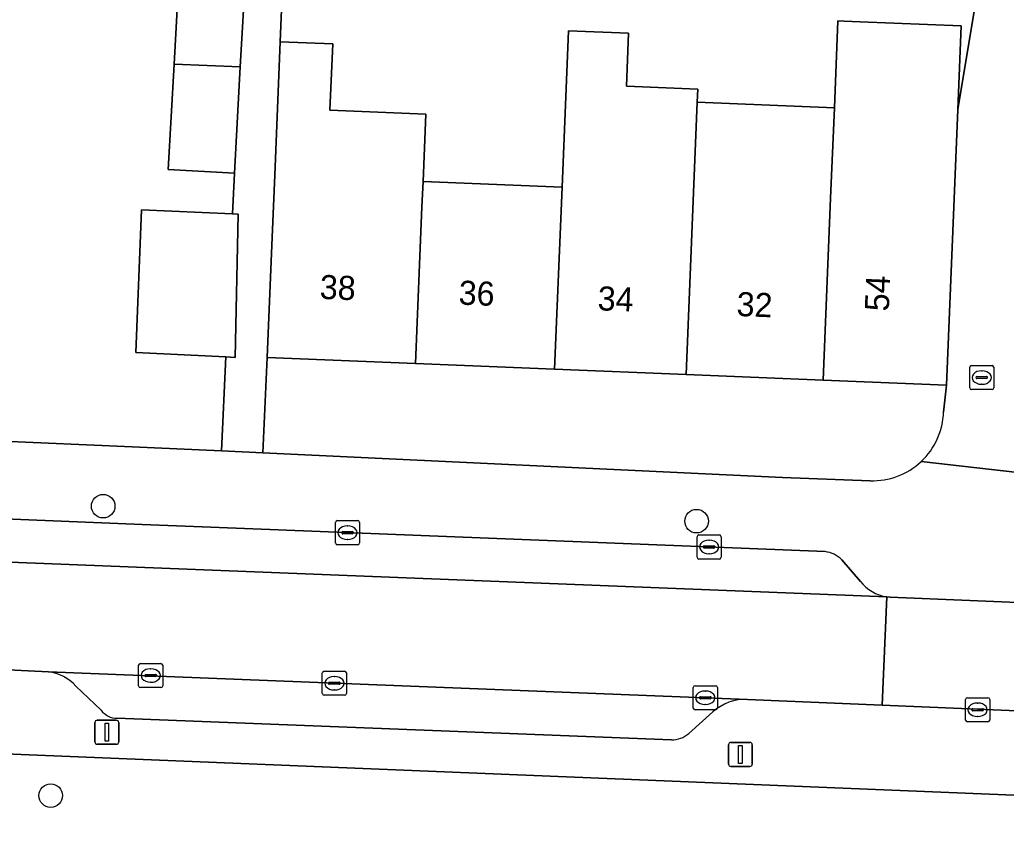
# Model space of a CAD drawing. Extents: x 159817 to 160765, y 380688 to 381638.
# Drawn here: x 160007.42 to 160048.41, y 380865.33 to 380898.7 of the extents above; entities that cross this region are included whole.
import ezdxf

# ---------------------------------------------------------------- set-up
doc = ezdxf.new("R2010")
doc.units = 0
for name, color, linetype in [('IMGEO_Berm_groen', 7, 'Continuous'), ('IMGEO_Boom', 7, 'Continuous'), ('IMGEO_Brandkraan', 7, 'Continuous'), ('IMGEO_Erf', 7, 'Continuous'), ('IMGEO_Kolk', 7, 'Continuous'), ('IMGEO_Lichtmast', 7, 'Continuous'), ('IMGEO_Muur', 7, 'Continuous'), ('IMGEO_Pand', 7, 'Continuous'), ('IMGEO_Pand_nummerreeks', 7, 'Continuous'), ('IMGEO_Parkeervlak_open', 7, 'Continuous'), ('IMGEO_Rijbaan_lokaal_open', 7, 'Continuous'), ('IMGEO_Rioolput', 7, 'Continuous'), ('IMGEO_Voetpad_open', 7, 'Continuous')]:
    doc.layers.add(name, color=color, linetype=linetype)

msp = doc.modelspace()

# ---------------------------------------------------------------- linework, layer by layer
at = {"layer": 'IMGEO_Berm_groen'}
msp.add_lwpolyline([(160170.952, 380848.196), (160169.444, 380861.549), (160005.773, 380868.257), (159996.586, 380868.629), (159996.603, 380869.516), (159993.946, 380869.644), (159993.895, 380868.739), (159985.923, 380869.026)], dxfattribs=at)
at = {"layer": 'IMGEO_Boom'}
for centre in [(160010.889, 380878.497), (160035.543, 380877.875), (160008.708, 380866.477)]:
    msp.add_circle(centre, 0.489, dxfattribs=at)
at = {"layer": 'IMGEO_Brandkraan'}
for p, q in [((160046.891, 380883.415), (160046.891, 380884.267)), ((160046.966, 380884.341), (160047.818, 380884.341)), ((160047.379, 380884.121), (160047.404, 380884.121)), ((160047.892, 380884.267), (160047.892, 380883.415)), ((160047.15, 380883.835), (160047.15, 380883.847)), ((160047.588, 380883.798), (160047.19, 380883.798)), ((160047.193, 380883.884), (160047.591, 380883.884)), ((160047.634, 380883.847), (160047.634, 380883.835)), ((160047.818, 380883.341), (160046.966, 380883.341)), ((160047.402, 380883.561), (160047.377, 380883.561))]:
    msp.add_line(p, q, dxfattribs=at)
for points in [[(160046.891, 380883.415), (160046.891, 380884.267)], [(160046.966, 380884.341), (160047.818, 380884.341)], [(160047.892, 380884.267), (160047.892, 380883.415)], [(160047.818, 380883.341), (160046.966, 380883.341)]]:
    msp.add_lwpolyline(points, dxfattribs=at)
for centre, radius, start, end in [((160046.968, 380884.265), 0.0765, 91.552, 178.448), ((160046.968, 380884.265), 0.0765, 91.552, 178.448), ((160047.816, 380884.265), 0.0765, 1.552, 88.448), ((160047.816, 380884.265), 0.0765, 1.552, 88.448), ((160047.19, 380883.844), 0.0403, 85.8775, 175.7526), ((160047.187, 380883.834), 0.0366, 178.938, 274.7102), ((160047.591, 380883.841), 0.043, 264.8664, 352.4533), ((160047.595, 380883.846), 0.0386, 1.7309, 96.639), ((160046.968, 380883.417), 0.0765, 181.552, 268.448), ((160046.968, 380883.417), 0.0765, 181.552, 268.448), ((160047.816, 380883.417), 0.0765, 271.552, 358.448), ((160047.816, 380883.417), 0.0765, 271.552, 358.448)]:
    msp.add_arc(centre, radius, start, end, dxfattribs=at)
for centre, major_axis, ratio, start_param, end_param in [((160047.378, 380883.841), (-0.387, 0.002), 0.722429, 4.712389, 7.853982), ((160047.403, 380883.841), (-0.39, 0.002), 0.717154, 1.570796, 4.712389)]:
    msp.add_ellipse(centre, major_axis=major_axis, ratio=ratio, start_param=start_param, end_param=end_param, dxfattribs=at)
at = {"layer": 'IMGEO_Erf'}
for points in [[(159989.985, 380938.498), (159987.614, 380882.024), (159996.902, 380881.622), (160012.088, 380880.965), (160015.8, 380880.79), (160015.984, 380884.697), (160012.245, 380884.873), (160012.483, 380890.803), (160016.263, 380890.632), (160016.34, 380892.325), (160013.59, 380892.478), (160013.833, 380896.854), (160014.06, 380900.928), (160016.809, 380900.776), (160016.883, 380904.187), (160014.133, 380904.34), (160014.376, 380908.716), (160014.603, 380912.79)], [(160018.787, 380910.907), (160018.244, 380897.786), (160020.426, 380897.696), (160020.312, 380894.948), (160024.293, 380894.783), (160024.178, 380891.985), (160029.955, 380891.748), (160030.22, 380898.242), (160032.718, 380898.14), (160032.628, 380895.941), (160035.594, 380895.82), (160035.572, 380895.281), (160041.268, 380895.047), (160041.416, 380898.652), (160041.675, 380898.642), (160042.335, 380898.615), (160046.538, 380898.442), (160046.395, 380894.967), (160047.716, 380902.893)], [(160045.925, 380883.518), (160040.804, 380883.728), (160035.109, 380883.962), (160029.646, 380884.187), (160023.868, 380884.424), (160017.704, 380884.677), (160017.517, 380880.709), (160039.11, 380879.69), (160042.759, 380879.556)], [(160045.805, 380882.405), (160045.925, 380883.518)]]:
    msp.add_lwpolyline(points, dxfattribs=at)
for centre, radius, start, end in [((160042.866, 380882.495), 2.94, 313.0697, 358.2481), ((160042.866, 380882.492), 2.938, 267.9062, 313.1049)]:
    msp.add_arc(centre, radius, start, end, dxfattribs=at)
at = {"layer": 'IMGEO_Kolk'}
for p, q in [((160020.616, 380877.897), (160021.468, 380877.897)), ((160020.541, 380876.971), (160020.541, 380877.823)), ((160021.029, 380877.677), (160021.054, 380877.677)), ((160021.542, 380877.823), (160021.542, 380876.971)), ((160020.8, 380877.391), (160020.8, 380877.403)), ((160021.238, 380877.354), (160020.84, 380877.354)), ((160020.843, 380877.44), (160021.241, 380877.44)), ((160021.052, 380877.117), (160021.027, 380877.117)), ((160021.284, 380877.403), (160021.284, 380877.391)), ((160035.563, 380876.377), (160035.563, 380877.229)), ((160035.638, 380877.303), (160036.49, 380877.303)), ((160036.051, 380877.083), (160036.076, 380877.083)), ((160036.564, 380877.229), (160036.564, 380876.377)), ((160021.468, 380876.897), (160020.616, 380876.897)), ((160035.822, 380876.797), (160035.822, 380876.809)), ((160036.26, 380876.76), (160035.862, 380876.76)), ((160035.865, 380876.846), (160036.263, 380876.846)), ((160036.306, 380876.809), (160036.306, 380876.797)), ((160036.49, 380876.303), (160035.638, 380876.303)), ((160036.074, 380876.523), (160036.049, 380876.523)), ((160019.994, 380870.718), (160019.994, 380871.57)), ((160020.069, 380871.644), (160020.921, 380871.644)), ((160020.482, 380871.424), (160020.507, 380871.424)), ((160020.995, 380871.57), (160020.995, 380870.718)), ((160020.253, 380871.138), (160020.253, 380871.15)), ((160020.691, 380871.101), (160020.293, 380871.101)), ((160020.296, 380871.187), (160020.694, 380871.187)), ((160020.737, 380871.15), (160020.737, 380871.138)), ((160035.406, 380870.115), (160035.406, 380870.967)), ((160035.481, 380871.041), (160036.333, 380871.041)), ((160036.407, 380870.967), (160036.407, 380870.115)), ((160020.921, 380870.644), (160020.069, 380870.644)), ((160020.505, 380870.864), (160020.48, 380870.864)), ((160035.665, 380870.535), (160035.665, 380870.547)), ((160035.708, 380870.584), (160036.106, 380870.584)), ((160035.894, 380870.821), (160035.919, 380870.821)), ((160036.149, 380870.547), (160036.149, 380870.535)), ((160036.103, 380870.498), (160035.705, 380870.498)), ((160035.917, 380870.261), (160035.892, 380870.261)), ((160036.333, 380870.041), (160035.481, 380870.041))]:
    msp.add_line(p, q, dxfattribs=at)
for points in [[(160020.616, 380877.897), (160021.468, 380877.897)], [(160020.541, 380876.971), (160020.541, 380877.823)], [(160021.542, 380877.823), (160021.542, 380876.971)], [(160035.563, 380876.377), (160035.563, 380877.229)], [(160035.638, 380877.303), (160036.49, 380877.303)], [(160036.564, 380877.229), (160036.564, 380876.377)], [(160021.468, 380876.897), (160020.616, 380876.897)], [(160036.49, 380876.303), (160035.638, 380876.303)], [(160019.994, 380870.718), (160019.994, 380871.57)], [(160020.069, 380871.644), (160020.921, 380871.644)], [(160020.995, 380871.57), (160020.995, 380870.718)], [(160035.406, 380870.115), (160035.406, 380870.967)], [(160035.481, 380871.041), (160036.333, 380871.041)], [(160036.407, 380870.967), (160036.407, 380870.115)], [(160020.921, 380870.644), (160020.069, 380870.644)], [(160036.333, 380870.041), (160035.481, 380870.041)]]:
    msp.add_lwpolyline(points, dxfattribs=at)
for centre, radius, start, end in [((160020.618, 380877.821), 0.0765, 91.552, 178.448), ((160020.618, 380877.821), 0.0765, 91.552, 178.448), ((160021.466, 380877.821), 0.0765, 1.552, 88.448), ((160021.466, 380877.821), 0.0765, 1.552, 88.448), ((160020.84, 380877.4), 0.0403, 85.8775, 175.7526), ((160020.837, 380877.39), 0.0366, 178.938, 274.7102), ((160021.241, 380877.397), 0.043, 264.8664, 352.4533), ((160021.245, 380877.402), 0.0386, 1.7309, 96.639), ((160035.64, 380877.227), 0.0765, 91.552, 178.448), ((160035.64, 380877.227), 0.0765, 91.552, 178.448), ((160036.488, 380877.227), 0.0765, 1.552, 88.448), ((160036.488, 380877.227), 0.0765, 1.552, 88.448), ((160020.618, 380876.973), 0.0765, 181.552, 268.448), ((160020.618, 380876.973), 0.0765, 181.552, 268.448), ((160021.466, 380876.973), 0.0765, 271.552, 358.448), ((160021.466, 380876.973), 0.0765, 271.552, 358.448), ((160035.862, 380876.806), 0.0403, 85.8775, 175.7526), ((160035.859, 380876.796), 0.0366, 178.938, 274.7102), ((160036.263, 380876.803), 0.043, 264.8664, 352.4533), ((160036.267, 380876.808), 0.0386, 1.7309, 96.639), ((160035.64, 380876.379), 0.0765, 181.552, 268.448), ((160035.64, 380876.379), 0.0765, 181.552, 268.448), ((160036.488, 380876.379), 0.0765, 271.552, 358.448), ((160036.488, 380876.379), 0.0765, 271.552, 358.448), ((160020.071, 380871.568), 0.0765, 91.552, 178.448), ((160020.071, 380871.568), 0.0765, 91.552, 178.448), ((160020.919, 380871.568), 0.0765, 1.552, 88.448), ((160020.919, 380871.568), 0.0765, 1.552, 88.448), ((160020.293, 380871.147), 0.0403, 85.8775, 175.7526), ((160020.29, 380871.137), 0.0366, 178.938, 274.7102), ((160020.694, 380871.144), 0.043, 264.8664, 352.4533), ((160020.698, 380871.149), 0.0386, 1.7309, 96.639), ((160035.483, 380870.965), 0.0765, 91.552, 178.448), ((160035.483, 380870.965), 0.0765, 91.552, 178.448), ((160036.331, 380870.965), 0.0765, 1.552, 88.448), ((160036.331, 380870.965), 0.0765, 1.552, 88.448), ((160020.071, 380870.72), 0.0765, 181.552, 268.448), ((160020.071, 380870.72), 0.0765, 181.552, 268.448), ((160020.919, 380870.72), 0.0765, 271.552, 358.448), ((160020.919, 380870.72), 0.0765, 271.552, 358.448), ((160035.705, 380870.544), 0.0403, 85.8775, 175.7526), ((160035.702, 380870.534), 0.0366, 178.938, 274.7102), ((160036.106, 380870.541), 0.043, 264.8664, 352.4533), ((160036.11, 380870.546), 0.0386, 1.7309, 96.639), ((160035.483, 380870.117), 0.0765, 181.552, 268.448), ((160035.483, 380870.117), 0.0765, 181.552, 268.448), ((160036.331, 380870.117), 0.0765, 271.552, 358.448), ((160036.331, 380870.117), 0.0765, 271.552, 358.448)]:
    msp.add_arc(centre, radius, start, end, dxfattribs=at)
for centre, major_axis, ratio, start_param, end_param in [((160021.028, 380877.397), (-0.387, 0.002), 0.722429, 4.712389, 7.853982), ((160021.053, 380877.397), (-0.39, 0.002), 0.717154, 1.570796, 4.712389), ((160036.05, 380876.803), (-0.387, 0.002), 0.722429, 4.712389, 7.853982), ((160036.075, 380876.803), (-0.39, 0.002), 0.717154, 1.570796, 4.712389), ((160020.481, 380871.144), (-0.387, 0.002), 0.722429, 4.712389, 7.853982), ((160020.506, 380871.144), (-0.39, 0.002), 0.717154, 1.570796, 4.712389), ((160035.893, 380870.541), (-0.387, 0.002), 0.722429, 4.712389, 7.853982), ((160035.918, 380870.541), (-0.39, 0.002), 0.717154, 1.570796, 4.712389)]:
    msp.add_ellipse(centre, major_axis=major_axis, ratio=ratio, start_param=start_param, end_param=end_param, dxfattribs=at)
at = {"layer": 'IMGEO_Lichtmast'}
for p, q in [((160010.545, 380868.707), (160010.545, 380869.507)), ((160010.545, 380869.507), (160010.545, 380868.707)), ((160010.645, 380869.607), (160011.435, 380869.607)), ((160011.435, 380869.607), (160010.645, 380869.607)), ((160011.535, 380869.507), (160011.535, 380868.707)), ((160011.535, 380868.707), (160011.535, 380869.507)), ((160011.435, 380868.607), (160010.645, 380868.607)), ((160010.645, 380868.607), (160011.435, 380868.607)), ((160036.87, 380867.787), (160036.87, 380868.587)), ((160036.87, 380868.587), (160036.87, 380867.787)), ((160036.97, 380868.687), (160037.76, 380868.687)), ((160037.76, 380868.687), (160036.97, 380868.687)), ((160037.86, 380868.587), (160037.86, 380867.787)), ((160037.86, 380867.787), (160037.86, 380868.587)), ((160037.76, 380867.687), (160036.97, 380867.687)), ((160036.97, 380867.687), (160037.76, 380867.687))]:
    msp.add_line(p, q, dxfattribs=at)
for points in [[(160010.965, 380869.482), (160011.115, 380869.482), (160011.115, 380868.732), (160010.965, 380868.732), (160010.965, 380869.482)], [(160037.29, 380868.562), (160037.44, 380868.562), (160037.44, 380867.812), (160037.29, 380867.812), (160037.29, 380868.562)]]:
    msp.add_lwpolyline(points, dxfattribs=at)
for centre, start, end in [((160010.645, 380869.507), 90, 180), ((160010.645, 380869.507), 90, 180), ((160011.435, 380869.507), 0, 90), ((160011.435, 380869.507), 360, 90), ((160010.645, 380868.707), 180, 270), ((160010.645, 380868.707), 180, 270), ((160011.435, 380868.707), 270, 0), ((160011.435, 380868.707), 270, 0), ((160036.97, 380868.587), 90, 180), ((160036.97, 380868.587), 90, 180), ((160037.76, 380868.587), 0, 90), ((160037.76, 380868.587), 360, 90), ((160036.97, 380867.787), 180, 270), ((160036.97, 380867.787), 180, 270), ((160037.76, 380867.787), 270, 0), ((160037.76, 380867.787), 270, 0)]:
    msp.add_arc(centre, 0.1, start, end, dxfattribs=at)
at = {"layer": 'IMGEO_Muur'}
for points in [[(160047.716, 380902.893), (160046.395, 380894.967)], [(160012.088, 380880.965), (159996.902, 380881.622)]]:
    msp.add_lwpolyline(points, dxfattribs=at)
at = {"layer": 'IMGEO_Pand'}
for points in [[(160013.833, 380896.854), (160016.585, 380896.738), (160016.809, 380900.776), (160014.06, 380900.928)], [(160046.395, 380894.967), (160046.538, 380898.442), (160042.335, 380898.615), (160041.675, 380898.642), (160041.416, 380898.652), (160041.268, 380895.047), (160041.114, 380891.289), (160040.804, 380883.728), (160045.925, 380883.518)], [(160035.419, 380891.523), (160035.572, 380895.281), (160035.594, 380895.82), (160032.628, 380895.941), (160032.718, 380898.14), (160030.22, 380898.242), (160029.955, 380891.748), (160029.646, 380884.187), (160035.109, 380883.962)], [(160024.178, 380891.985), (160024.293, 380894.783), (160020.312, 380894.948), (160020.426, 380897.696), (160018.244, 380897.786), (160018.015, 380892.238), (160017.909, 380889.673), (160017.704, 380884.677), (160023.868, 380884.424), (160024.135, 380890.932)], [(160013.833, 380896.854), (160013.59, 380892.478), (160016.34, 380892.325), (160016.585, 380896.738)], [(160041.114, 380891.289), (160041.268, 380895.047), (160035.572, 380895.281), (160035.419, 380891.523), (160035.109, 380883.962), (160040.804, 380883.728)], [(160029.955, 380891.748), (160024.178, 380891.985), (160024.135, 380890.932), (160023.868, 380884.424), (160029.646, 380884.187)], [(160016.495, 380890.621), (160016.263, 380890.632), (160012.483, 380890.803), (160012.245, 380884.873), (160015.984, 380884.697), (160016.372, 380884.679)]]:
    msp.add_lwpolyline(points, close=True, dxfattribs=at)
at = {"layer": 'IMGEO_Parkeervlak_open'}
for points in [[(160040.886, 380876.611), (160015.362, 380877.62), (160012.514, 380877.733), (160004.085, 380878.085), (159990.838, 380878.596)], [(159987.534, 380876.872), (159992.758, 380876.736), (160000, 380876.443), (160043.442, 380874.732)], [(160042.349, 380875.375), (160041.58, 380876.271)], [(160037.659, 380870.474), (160008.619, 380871.611)], [(160009.754, 380871.026), (160010.803, 380870.019)], [(160035.22, 380869.054), (160036.215, 380869.951)], [(160011.462, 380869.688), (160034.506, 380868.789)]]:
    msp.add_lwpolyline(points, dxfattribs=at)
for centre, radius, start, end in [((160040.737, 380875.429), 1.191, 44.9736, 82.8247), ((160043.739, 380876.487), 1.78, 218.6585, 260.4058), ((160008.396, 380869.784), 1.841, 42.437, 83.0281), ((160037.588, 380868.416), 2.059, 88.0154, 131.8042), ((160011.48, 380870.545), 0.857, 217.8393, 268.8221), ((160034.49, 380869.926), 1.137, 270.7959, 309.9288)]:
    msp.add_arc(centre, radius, start, end, dxfattribs=at)
at = {"layer": 'IMGEO_Rijbaan_lokaal_open'}
for points in [[(160008.619, 380871.611), (160037.659, 380870.474), (160043.26, 380870.238), (160043.442, 380874.732), (160000, 380876.443), (159992.758, 380876.736), (159987.534, 380876.872), (159987.308, 380871.906), (160001.409, 380871.913), (160005.518, 380871.771)], [(160050.208, 380874.443), (160043.593, 380874.713), (160043.442, 380874.732), (160043.26, 380870.238), (160054.79, 380869.752), (160054.971, 380874.246), (160054.135, 380874.282)]]:
    msp.add_lwpolyline(points, close=True, dxfattribs=at)
at = {"layer": 'IMGEO_Rioolput'}
for p, q in [((160012.362, 380871.039), (160012.362, 380871.891)), ((160012.437, 380871.965), (160013.289, 380871.965)), ((160012.85, 380871.745), (160012.875, 380871.745)), ((160013.363, 380871.891), (160013.363, 380871.039)), ((160012.621, 380871.459), (160012.621, 380871.471)), ((160013.059, 380871.422), (160012.661, 380871.422)), ((160012.664, 380871.508), (160013.062, 380871.508)), ((160013.105, 380871.471), (160013.105, 380871.459)), ((160013.289, 380870.965), (160012.437, 380870.965)), ((160012.873, 380871.185), (160012.848, 380871.185)), ((160046.795, 380870.542), (160047.647, 380870.542)), ((160046.72, 380869.616), (160046.72, 380870.468)), ((160047.208, 380870.322), (160047.233, 380870.322)), ((160047.721, 380870.468), (160047.721, 380869.616)), ((160046.979, 380870.036), (160046.979, 380870.048)), ((160047.417, 380869.999), (160047.019, 380869.999)), ((160047.022, 380870.085), (160047.42, 380870.085)), ((160047.231, 380869.762), (160047.206, 380869.762)), ((160047.463, 380870.048), (160047.463, 380870.036)), ((160047.647, 380869.542), (160046.795, 380869.542))]:
    msp.add_line(p, q, dxfattribs=at)
for points in [[(160012.362, 380871.039), (160012.362, 380871.891)], [(160012.437, 380871.965), (160013.289, 380871.965)], [(160013.363, 380871.891), (160013.363, 380871.039)], [(160013.289, 380870.965), (160012.437, 380870.965)], [(160046.795, 380870.542), (160047.647, 380870.542)], [(160046.72, 380869.616), (160046.72, 380870.468)], [(160047.721, 380870.468), (160047.721, 380869.616)], [(160047.647, 380869.542), (160046.795, 380869.542)]]:
    msp.add_lwpolyline(points, dxfattribs=at)
for centre, radius, start, end in [((160012.439, 380871.889), 0.0765, 91.552, 178.448), ((160012.439, 380871.889), 0.0765, 91.552, 178.448), ((160013.287, 380871.889), 0.0765, 1.552, 88.448), ((160013.287, 380871.889), 0.0765, 1.552, 88.448), ((160012.661, 380871.468), 0.0403, 85.8775, 175.7526), ((160012.658, 380871.458), 0.0366, 178.938, 274.7102), ((160013.062, 380871.465), 0.043, 264.8664, 352.4533), ((160013.066, 380871.47), 0.0386, 1.7309, 96.639), ((160012.439, 380871.041), 0.0765, 181.552, 268.448), ((160012.439, 380871.041), 0.0765, 181.552, 268.448), ((160013.287, 380871.041), 0.0765, 271.552, 358.448), ((160013.287, 380871.041), 0.0765, 271.552, 358.448), ((160046.797, 380870.466), 0.0765, 91.552, 178.448), ((160046.797, 380870.466), 0.0765, 91.552, 178.448), ((160047.645, 380870.466), 0.0765, 1.552, 88.448), ((160047.645, 380870.466), 0.0765, 1.552, 88.448), ((160047.019, 380870.045), 0.0403, 85.8775, 175.7526), ((160047.016, 380870.035), 0.0366, 178.938, 274.7102), ((160047.42, 380870.042), 0.043, 264.8664, 352.4533), ((160047.424, 380870.047), 0.0386, 1.7309, 96.639), ((160046.797, 380869.618), 0.0765, 181.552, 268.448), ((160046.797, 380869.618), 0.0765, 181.552, 268.448), ((160047.645, 380869.618), 0.0765, 271.552, 358.448), ((160047.645, 380869.618), 0.0765, 271.552, 358.448)]:
    msp.add_arc(centre, radius, start, end, dxfattribs=at)
for centre, major_axis, ratio, start_param, end_param in [((160012.849, 380871.465), (-0.387, 0.002), 0.722429, 4.712389, 7.853982), ((160012.874, 380871.465), (-0.39, 0.002), 0.717154, 1.570796, 4.712389), ((160047.207, 380870.042), (-0.387, 0.002), 0.722429, 4.712389, 7.853982), ((160047.232, 380870.042), (-0.39, 0.002), 0.717154, 1.570796, 4.712389)]:
    msp.add_ellipse(centre, major_axis=major_axis, ratio=ratio, start_param=start_param, end_param=end_param, dxfattribs=at)
at = {"layer": 'IMGEO_Voetpad_open'}
for points in [[(160065.745, 380985.967), (160063.991, 380986.313), (160062.205, 380986.636), (160059.054, 380968.418), (160058.623, 380965.925), (160054.645, 380942.926), (160054.211, 380940.418), (160048.492, 380907.352), (160048.235, 380905.865), (160047.716, 380902.893), (160046.395, 380894.967), (160045.925, 380883.518), (160045.805, 380882.405)], [(160016.809, 380900.776), (160016.585, 380896.738), (160016.34, 380892.325), (160016.263, 380890.632), (160016.495, 380890.621), (160016.372, 380884.679), (160015.984, 380884.697), (160015.8, 380880.79), (160017.517, 380880.709), (160017.704, 380884.677), (160017.909, 380889.673), (160018.015, 380892.238), (160018.244, 380897.786), (160018.787, 380910.907)], [(160044.874, 380880.347), (160048.893, 380879.896), (160050.041, 380893.234)], [(160017.517, 380880.709), (160015.8, 380880.79), (160012.088, 380880.965), (159996.902, 380881.622), (159987.614, 380882.024), (159984.501, 380882.6)], [(160042.759, 380879.556), (160039.11, 380879.69), (160017.517, 380880.709)], [(160043.442, 380874.732), (160043.593, 380874.713), (160050.208, 380874.443), (160050.429, 380879.83), (160048.893, 380879.896), (160044.874, 380880.347)], [(159990.838, 380878.596), (160004.085, 380878.085), (160012.514, 380877.733), (160015.362, 380877.62), (160040.886, 380876.611)], [(160041.58, 380876.271), (160042.349, 380875.375)], [(160008.619, 380871.611), (160005.518, 380871.771), (160001.409, 380871.913), (159987.308, 380871.906), (159985.324, 380871.897), (159984.118, 380871.793)], [(160010.803, 380870.019), (160009.754, 380871.026)], [(160057.268, 380869.647), (160054.79, 380869.752), (160043.26, 380870.238), (160037.659, 380870.474)], [(160036.215, 380869.951), (160035.22, 380869.054)], [(159985.923, 380869.026), (159993.895, 380868.739), (159993.946, 380869.644), (159996.603, 380869.516), (159996.586, 380868.629), (160005.773, 380868.257), (160169.444, 380861.549), (160169.293, 380862.879), (160168.811, 380864.208)], [(160034.506, 380868.789), (160011.462, 380869.688)]]:
    msp.add_lwpolyline(points, dxfattribs=at)
for centre, radius, start, end in [((160042.866, 380882.495), 2.94, 313.0697, 358.2481), ((160042.866, 380882.492), 2.938, 267.9062, 313.1049), ((160040.737, 380875.429), 1.191, 44.9736, 82.8247), ((160043.739, 380876.487), 1.78, 218.6585, 260.4058), ((160008.396, 380869.784), 1.841, 42.437, 83.0281), ((160037.588, 380868.416), 2.059, 88.0154, 131.8042), ((160011.48, 380870.545), 0.857, 217.8393, 268.8221), ((160034.49, 380869.926), 1.137, 270.7959, 309.9288)]:
    msp.add_arc(centre, radius, start, end, dxfattribs=at)

# ---------------------------------------------------------------- texts
at = {"layer": 'IMGEO_Pand_nummerreeks'}
for s, rotation, p in [('38', 357.6509, (160019.873, 380887.11)), ('36', 357.6509, (160025.645, 380886.873)), ('54', 87.6511, (160043.529, 380886.576)), ('34', 357.6509, (160031.42, 380886.636)), ('32', 357.6509, (160037.192, 380886.399))]:
    msp.add_text(s, height=1, rotation=rotation, dxfattribs=at).set_placement(p)

doc.saveas('drawing.dxf')
